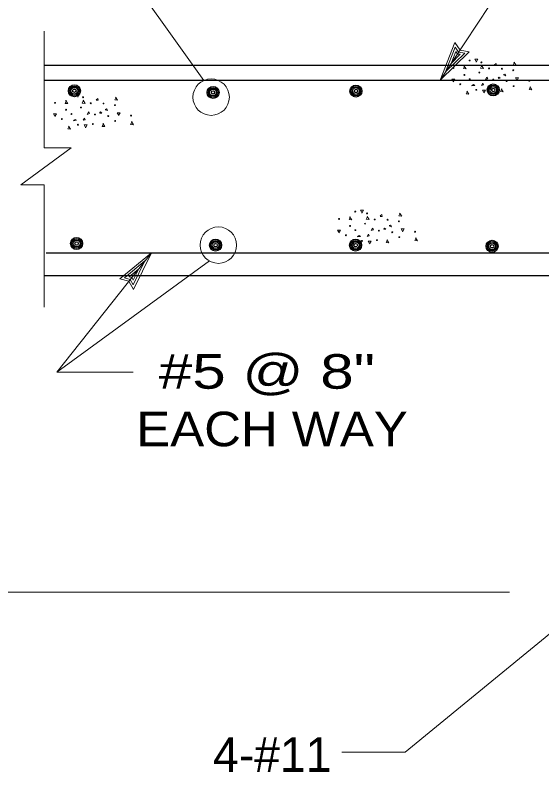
# Model space of a CAD drawing. Extents: x -28.1 to 13.9, y -16.1 to 13.9.
# Drawn here: x -23.93 to -22.028, y -12.112 to -9.376 of the extents above; entities that cross this region are included whole.
import ezdxf
from ezdxf.enums import TextEntityAlignment as Align

# ---------------------------------------------------------------- set-up
doc = ezdxf.new("R2010")
doc.units = 0
doc.header["$LTSCALE"] = 0.05
doc.layers.add('1', color=7, linetype='Continuous', lineweight=13)
doc.layers.add('2', color=7, linetype='Continuous', lineweight=13)

msp = doc.modelspace()

# ---------------------------------------------------------------- linework, layer by layer
at = {"layer": '1'}
for p, q in [((-23.82528, -9.85584), (-23.82528, -9.43484)), ((-22.39528, -9.61184), (-22.34228, -9.47484)), ((-22.37528, -9.58084), (-22.34028, -9.49184)), ((-22.34028, -9.49184), (-22.32828, -9.50984)), ((-22.39528, -9.61184), (-22.29028, -9.50884)), ((-22.37528, -9.58084), (-22.30628, -9.51384)), ((-22.35528, -9.55084), (-22.33828, -9.50784)), ((-22.35528, -9.55084), (-22.32228, -9.51784)), ((-22.33828, -9.50784), (-22.33228, -9.51684)), ((-22.33228, -9.51684), (-22.32228, -9.51784)), ((-22.32828, -9.50984), (-22.30628, -9.51384)), ((-23.90928, -9.98984), (-23.72828, -9.85584)), ((-23.82528, -9.85584), (-23.72828, -9.85584)), ((-23.90928, -9.98984), (-23.82528, -9.98984)), ((-23.82528, -10.43184), (-23.82528, -9.98984)), ((-23.43828, -10.23584), (-23.78028, -10.66684)), ((-23.43828, -10.23584), (-23.55228, -10.32984)), ((-23.43828, -10.23584), (-23.50328, -10.36784)), ((-23.46128, -10.26484), (-23.53528, -10.32584)), ((-23.46128, -10.26484), (-23.50428, -10.35084)), ((-23.48328, -10.29284), (-23.51828, -10.32284)), ((-23.48328, -10.29284), (-23.50428, -10.33484)), ((-23.51428, -10.33184), (-23.53528, -10.32584)), ((-23.50928, -10.32484), (-23.51828, -10.32284)), ((-23.50428, -10.35084), (-23.51428, -10.33184)), ((-23.50428, -10.33484), (-23.50928, -10.32484)), ((-22.14428, -11.46184), (-25.22828, -11.46184))]:
    msp.add_line(p, q, dxfattribs=at)
at = {"layer": '1', "lineweight": 25}
for p, q in [((-23.82428, -9.55684), (-20.57028, -9.55684)), ((-23.82428, -9.61184), (-20.67028, -9.61184)), ((-23.81828, -10.23584), (-20.77528, -10.23584)), ((-23.82528, -10.31784), (-21.99128, -10.31784))]:
    msp.add_line(p, q, dxfattribs=at)
at = {"layer": '1'}
for points in [[(-23.24928, -9.61284), (-23.91828, -8.67384), (-23.65628, -8.67384)], [(-22.39528, -9.61184), (-21.81528, -8.73284), (-21.56628, -8.73284)], [(-22.34228, -9.47484), (-22.32328, -9.50284), (-22.29028, -9.50884)], [(-23.22828, -10.26484), (-23.78028, -10.66684), (-23.50428, -10.66684)], [(-23.50328, -10.36784), (-23.51928, -10.33784), (-23.55228, -10.32984)], [(-21.61628, -11.29784), (-22.52128, -12.04084), (-22.75028, -12.04084)]]:
    msp.add_lwpolyline(points, dxfattribs=at)
at = {"layer": '1', "lineweight": 25}
for centre, radius in [((-23.71633, -9.64977), 0.02168), ((-22.20333, -9.64677), 0.02168), ((-23.71633, -9.64977), 0.01681), ((-23.71633, -9.64977), 0.01233), ((-23.71633, -9.64977), 0.00623), ((-23.21533, -9.65577), 0.02168), ((-23.21533, -9.65577), 0.01681), ((-23.21533, -9.65577), 0.01233), ((-23.21533, -9.65577), 0.00623), ((-22.69933, -9.65077), 0.02168), ((-22.69933, -9.65077), 0.01681), ((-22.69933, -9.65077), 0.01233), ((-22.69933, -9.65077), 0.00623), ((-22.20333, -9.64677), 0.01681), ((-22.20333, -9.64677), 0.01233), ((-22.20333, -9.64677), 0.00623), ((-23.70833, -10.20177), 0.02168), ((-23.70833, -10.20177), 0.01681), ((-23.70833, -10.20177), 0.01233), ((-23.70833, -10.20177), 0.00623), ((-23.20633, -10.20777), 0.02168), ((-23.20633, -10.20777), 0.01681), ((-23.20633, -10.20777), 0.01233), ((-23.20633, -10.20777), 0.00623), ((-22.70033, -10.20777), 0.02168), ((-22.70033, -10.20777), 0.01681), ((-22.70033, -10.20777), 0.01233), ((-22.70033, -10.20777), 0.00623), ((-22.20733, -10.21177), 0.02168), ((-22.20733, -10.21177), 0.01681), ((-22.20733, -10.21177), 0.01233), ((-22.20733, -10.21177), 0.00623)]:
    msp.add_circle(centre, radius, dxfattribs=at)
at = {"layer": '1'}
for centre in [(-23.22228, -9.67284), (-23.19628, -10.20784)]:
    msp.add_circle(centre, 0.0658, dxfattribs=at)
at = {"layer": '2'}
for p, q in [((-22.19904, -9.55631), (-22.19304, -9.55131)), ((-23.63804, -9.68231), (-23.63204, -9.67731)), ((-22.61204, -10.10231), (-22.60604, -10.09731))]:
    msp.add_line(p, q, dxfattribs=at)
for points in [[(-22.26504, -9.54431), (-22.27004, -9.53531), (-22.25904, -9.53531), (-22.26504, -9.54631)], [(-22.12604, -9.54631), (-22.13104, -9.55631), (-22.12104, -9.55731), (-22.12904, -9.54631)], [(-22.30604, -9.55931), (-22.31104, -9.56931), (-22.30104, -9.57031), (-22.30904, -9.55931)], [(-22.24404, -9.55831), (-22.24904, -9.56831), (-22.23804, -9.56931), (-22.24604, -9.55831)], [(-22.19304, -9.55131), (-22.19104, -9.55831), (-22.19904, -9.55831)], [(-22.18604, -9.60431), (-22.18304, -9.60031), (-22.17804, -9.60431), (-22.18504, -9.60531)], [(-22.16604, -9.59131), (-22.16104, -9.58931), (-22.15804, -9.59531), (-22.16604, -9.59231)], [(-22.34804, -9.61531), (-22.35304, -9.60731), (-22.34204, -9.60731), (-22.34804, -9.61731)], [(-22.27904, -9.63031), (-22.27404, -9.62731), (-22.27004, -9.63031), (-22.28204, -9.63231)], [(-22.11804, -9.61131), (-22.12304, -9.60331), (-22.11204, -9.60331), (-22.11804, -9.61331)], [(-22.29604, -9.65131), (-22.30104, -9.66131), (-22.29104, -9.66231), (-22.29904, -9.65131)], [(-22.23704, -9.65631), (-22.24204, -9.64731), (-22.23104, -9.64731), (-22.23704, -9.65731)], [(-22.17204, -9.64231), (-22.17704, -9.65231), (-22.16704, -9.65331), (-22.17504, -9.64231)], [(-22.06904, -9.63531), (-22.07404, -9.64531), (-22.06404, -9.64631), (-22.07104, -9.63531)], [(-23.70404, -9.67031), (-23.70904, -9.66131), (-23.69804, -9.66131), (-23.70404, -9.67231)], [(-23.63204, -9.67731), (-23.63004, -9.68431), (-23.63804, -9.68431)], [(-23.56504, -9.67231), (-23.57004, -9.68231), (-23.56004, -9.68331), (-23.56804, -9.67231)], [(-23.74504, -9.68531), (-23.75004, -9.69531), (-23.74004, -9.69631), (-23.74804, -9.68531)], [(-23.68304, -9.68431), (-23.68804, -9.69431), (-23.67704, -9.69531), (-23.68504, -9.68431)], [(-23.78704, -9.74131), (-23.79204, -9.73331), (-23.78104, -9.73331), (-23.78704, -9.74331)], [(-23.62504, -9.73031), (-23.62204, -9.72631), (-23.61704, -9.73031), (-23.62404, -9.73131)], [(-23.60504, -9.71731), (-23.60004, -9.71531), (-23.59704, -9.72131), (-23.60504, -9.71831)], [(-23.55704, -9.73731), (-23.56204, -9.72931), (-23.55104, -9.72931), (-23.55704, -9.73931)], [(-23.71804, -9.75631), (-23.71304, -9.75331), (-23.70904, -9.75631), (-23.72104, -9.75831)], [(-23.50804, -9.76131), (-23.51304, -9.77131), (-23.50304, -9.77231), (-23.51004, -9.76131)], [(-23.73504, -9.77731), (-23.74004, -9.78731), (-23.73004, -9.78831), (-23.73804, -9.77731)], [(-23.67604, -9.78231), (-23.68104, -9.77331), (-23.67004, -9.77331), (-23.67604, -9.78331)], [(-23.61104, -9.76831), (-23.61604, -9.77831), (-23.60604, -9.77931), (-23.61404, -9.76831)], [(-22.67804, -10.09031), (-22.68304, -10.08131), (-22.67204, -10.08131), (-22.67804, -10.09231)], [(-22.53904, -10.09231), (-22.54404, -10.10231), (-22.53404, -10.10331), (-22.54204, -10.09231)], [(-22.71904, -10.10531), (-22.72404, -10.11531), (-22.71404, -10.11631), (-22.72204, -10.10531)], [(-22.65704, -10.10431), (-22.66204, -10.11431), (-22.65104, -10.11531), (-22.65904, -10.10431)], [(-22.60604, -10.09731), (-22.60404, -10.10431), (-22.61204, -10.10431)], [(-22.59904, -10.15031), (-22.59604, -10.14631), (-22.59104, -10.15031), (-22.59804, -10.15131)], [(-22.57904, -10.13731), (-22.57404, -10.13531), (-22.57104, -10.14131), (-22.57904, -10.13831)], [(-22.76104, -10.16131), (-22.76604, -10.15331), (-22.75504, -10.15331), (-22.76104, -10.16331)], [(-22.69204, -10.17631), (-22.68704, -10.17331), (-22.68304, -10.17631), (-22.69504, -10.17831)], [(-22.53104, -10.15731), (-22.53604, -10.14931), (-22.52504, -10.14931), (-22.53104, -10.15931)], [(-22.70904, -10.19731), (-22.71404, -10.20731), (-22.70404, -10.20831), (-22.71204, -10.19731)], [(-22.65004, -10.20231), (-22.65504, -10.19331), (-22.64404, -10.19331), (-22.65004, -10.20331)], [(-22.58504, -10.18831), (-22.59004, -10.19831), (-22.58004, -10.19931), (-22.58804, -10.18831)], [(-22.48204, -10.18131), (-22.48704, -10.19131), (-22.47704, -10.19231), (-22.48404, -10.18131)]]:
    msp.add_lwpolyline(points, dxfattribs=at)
for points in [[(-22.23104, -9.60931), (-22.22604, -9.60031), (-22.22304, -9.60631)], [(-22.24604, -9.63031), (-22.24104, -9.62231), (-22.23804, -9.62831)], [(-23.67004, -9.73531), (-23.66504, -9.72631), (-23.66204, -9.73231)], [(-23.68504, -9.75631), (-23.68004, -9.74831), (-23.67704, -9.75431)], [(-22.64404, -10.15531), (-22.63904, -10.14631), (-22.63604, -10.15231)], [(-22.65904, -10.17631), (-22.65404, -10.16831), (-22.65104, -10.17431)]]:
    msp.add_lwpolyline(points, close=True, dxfattribs=at)
for centre in [(-22.28879, -9.54044), (-22.24604, -9.54719), (-22.34704, -9.56719), (-22.21829, -9.56894), (-22.17204, -9.56994), (-22.13079, -9.57569), (-22.30729, -9.59244), (-22.25354, -9.58419), (-22.32254, -9.62619), (-22.28804, -9.60769), (-22.20304, -9.60944), (-22.15504, -9.61519), (-22.07254, -9.61344), (-22.26454, -9.64644), (-22.21054, -9.64394), (-22.12979, -9.63294), (-23.72779, -9.66644), (-23.68504, -9.67319), (-23.78604, -9.69319), (-23.69254, -9.71019), (-23.65729, -9.69494), (-23.61104, -9.69594), (-23.56979, -9.70169), (-23.74629, -9.71844), (-23.72704, -9.73369), (-23.64204, -9.73544), (-23.51154, -9.73944), (-23.76154, -9.75219), (-23.59404, -9.74119), (-23.56879, -9.75894), (-23.70354, -9.77244), (-23.64954, -9.76994), (-22.70179, -10.08644), (-22.65904, -10.09319), (-22.76004, -10.11319), (-22.63129, -10.11494), (-22.58504, -10.11594), (-22.54379, -10.12169), (-22.72029, -10.13844), (-22.66654, -10.13019), (-22.73554, -10.17219), (-22.70104, -10.15369), (-22.61604, -10.15544), (-22.56804, -10.16119), (-22.48554, -10.15944), (-22.67754, -10.19244), (-22.62354, -10.18994), (-22.54279, -10.17894)]:
    msp.add_circle(centre, 0.00162, dxfattribs=at)

# ---------------------------------------------------------------- texts
at = {"layer": '1', "width": 1.3}
msp.add_text('#5 @ 8"', height=0.125, dxfattribs=at).set_placement((-23.41128, -10.72684))
at = {"layer": '1', "width": 1.1}
msp.add_text('EACH WAY', height=0.125, dxfattribs=at).set_placement((-23.00227, -10.93484), align=Align.CENTER)
at = {"layer": '1'}
msp.add_text('4-#11', height=0.125, dxfattribs=at).set_placement((-23.21528, -12.11184))

doc.saveas('drawing.dxf')
